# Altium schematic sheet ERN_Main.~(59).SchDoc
size A; SheetNumber: 1; SheetTotal: 4; SPICEModelCacheDBTNACQE: <root> / <DocumentId>DBTNACQE</DocumentId> / </root>
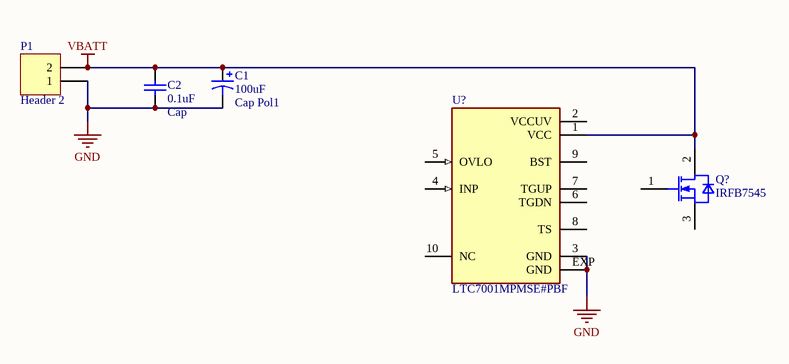
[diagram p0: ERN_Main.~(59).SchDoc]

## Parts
C1  Cap Pol1  value 100uF  [RB7.6-15]
C2  Cap  value 0.1uF  [RAD-0.3]
P1  Header 2  [HDR1X2]
Q?  IRFB7545  [IFX-PG-TO220-3-904]
U?  LTC7001MPMSE#PBF  [SOP50P490X110-11N]

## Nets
GND: C1.2 C2.1 P1.1 U?.3(GND) U?.EXP(GND)
VBATT: C1.1 C2.2 P1.2 Q?.2(DRAIN) U?.1(VCC)

Not connected (* = marked no-connect by the designer): Q? 1(GATE) 3(SOURCE); U? 2(VCCUV) 4(INP) 5(OVLO) 6(TGDN) 7(TGUP) 8(TS) 9(BST) 10(NC)

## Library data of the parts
C1 = Cap Pol1: Polarized Capacitor (Radial)
C2 = Cap: Capacitor
P1 = Header 2: Header, 2-Pin
Q? = IRFB7545: N-Channel 60V 95A; Insulated-Gate Field-Effect Transistor (IGFET), N-Channel, Enhancement, Body Diode, Pin 1 Gate, 2 Drain, 3 Source, 3 Pins; Manufacturer: Infineon Technologies
U? = LTC7001MPMSE#PBF: Fast 150V High Side NMOS Static Switch Driver; MF: Analog Devices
